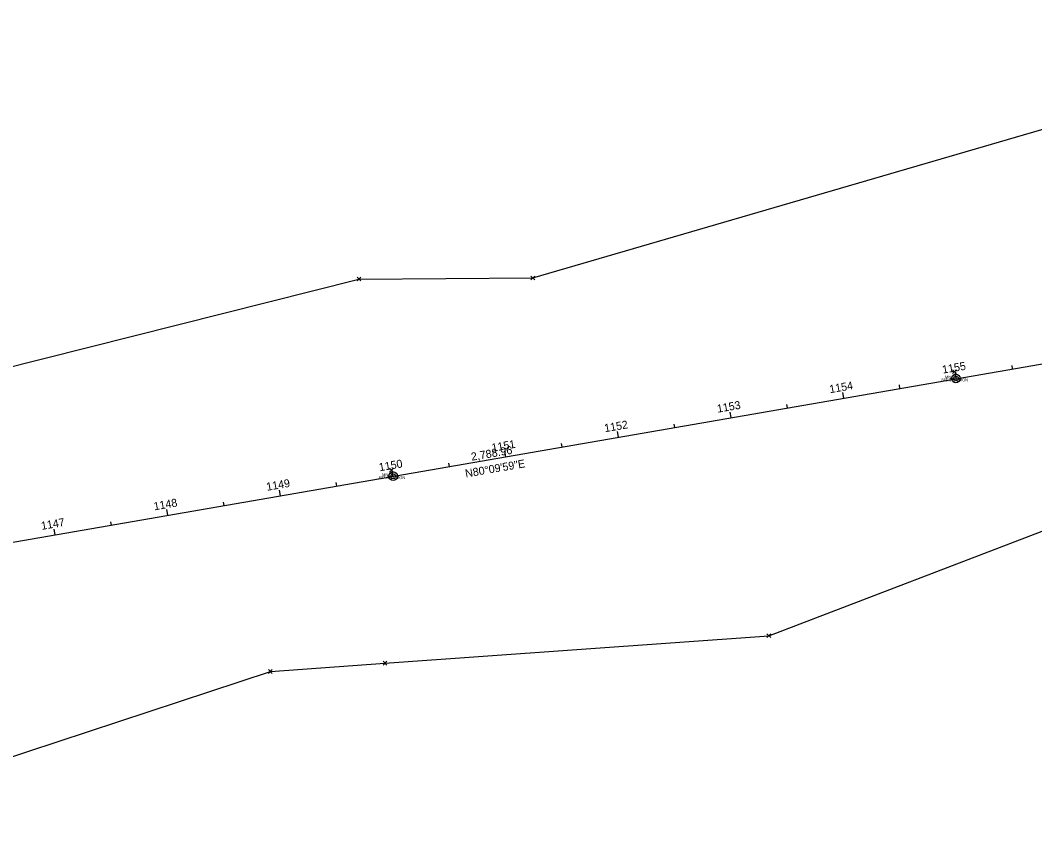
# Model space of a CAD drawing. Extents: x 2082101 to 2090447, y 708207 to 709766.
# Drawn here: x 2086260 to 2087148, y 708465 to 709174 of the extents above; entities that cross this region are included whole.
import ezdxf

# ---------------------------------------------------------------- set-up
doc = ezdxf.new("R2010")
doc.units = 0
for name, color, linetype in [('DR_X_Ditch', 7, 'Continuous'), ('GK_Drainage_Nodes', 7, 'Continuous'), ('SN_X_Public', 7, 'Continuous'), ('SV_X_Break_Lines', 7, 'Continuous'), ('SV_X_Mon_Cells_Found', 7, 'Continuous'), ('SV_X_Shot_Marker', 7, 'Continuous'), ('SV_X_Text_Comment', 7, 'Continuous'), ('SV_X_Text_Elevation', 7, 'Continuous'), ('SV_X_Text_Name', 7, 'Continuous'), ('SV_X_Toe_of_Slope', 7, 'Continuous'), ('VG_X_Cells', 7, 'Continuous')]:
    doc.layers.add(name, color=color, linetype=linetype)

msp = doc.modelspace()

# ---------------------------------------------------------------- linework, layer by layer
at = {"layer": 'DR_X_Ditch'}
for p, q in [((2086708.85, 708948.54), (2087481.72, 709173.84)), ((2085846.9, 708768.68), (2086556.78, 708947.55)), ((2086556.78, 708947.55), (2086708.85, 708948.54)), ((2086915.31, 708635.7), (2087248.47, 708762.97)), ((2086579.5, 708611.61), (2086915.31, 708635.7)), ((2086056.84, 708465.14), (2086479.26, 708604.37)), ((2086479.26, 708604.37), (2086579.5, 708611.61))]:
    msp.add_line(p, q, dxfattribs=at)
at = {"layer": 'GK_Drainage_Nodes'}
for p, q in [((2087128.59, 708869.05), (2087128.07, 708872.01)), ((2087079.32, 708860.51), (2087078.47, 708865.44)), ((2087030.06, 708851.98), (2087029.54, 708854.93)), ((2086980.79, 708843.44), (2086979.94, 708848.36)), ((2086931.52, 708834.9), (2086931.01, 708837.85)), ((2086882.26, 708826.36), (2086881.41, 708831.28)), ((2086832.99, 708817.82), (2086832.48, 708820.77)), ((2086783.73, 708809.28), (2086782.87, 708814.21)), ((2086734.46, 708800.74), (2086733.95, 708803.7)), ((2086685.2, 708792.2), (2086684.34, 708797.13)), ((2086635.93, 708783.66), (2086635.42, 708786.62)), ((2086586.67, 708775.12), (2086585.81, 708780.05)), ((2086488.14, 708758.04), (2086487.28, 708762.97)), ((2086537.4, 708766.58), (2086536.89, 708769.54)), ((2086389.61, 708740.96), (2086388.75, 708745.89)), ((2086438.87, 708749.5), (2086438.36, 708752.46)), ((2086291.07, 708723.89), (2086290.22, 708728.81)), ((2086340.34, 708732.42), (2086339.83, 708735.38))]:
    msp.add_line(p, q, dxfattribs=at)
at = {"layer": 'SV_X_Break_Lines'}
for p, q in [((2086707.18, 708946.87), (2086710.51, 708950.2)), ((2086707.18, 708950.2), (2086710.51, 708946.87)), ((2086555.11, 708945.88), (2086558.45, 708949.22)), ((2086555.11, 708949.22), (2086558.45, 708945.88)), ((2086913.64, 708634.03), (2086916.97, 708637.37)), ((2086913.64, 708637.37), (2086916.97, 708634.03)), ((2086577.84, 708609.94), (2086581.17, 708613.28)), ((2086577.84, 708613.28), (2086581.17, 708609.94)), ((2086477.6, 708602.7), (2086480.93, 708606.04)), ((2086477.6, 708606.04), (2086480.93, 708602.7))]:
    msp.add_line(p, q, dxfattribs=at)
at = {"layer": 'SV_X_Shot_Marker'}
msp.add_line((2085301.62, 708552.38), (2088049.6, 709028.7), dxfattribs=at)
at = {"layer": 'SV_X_Text_Name'}
for p, q in [((2087076.04, 708864.85), (2087079.38, 708868.19)), ((2087076.04, 708868.19), (2087079.38, 708864.85)), ((2086583.5, 708778.8), (2086586.84, 708782.13)), ((2086583.5, 708782.13), (2086586.84, 708778.8))]:
    msp.add_line(p, q, dxfattribs=at)
at = {"layer": 'SV_X_Toe_of_Slope'}
for centre, radius in [((2087079.01, 708860.62), 3.75), ((2087079.01, 708860.62), 2), ((2086586.66, 708775.09), 3.75), ((2086586.66, 708775.09), 2)]:
    msp.add_circle(centre, radius, dxfattribs=at)

# ---------------------------------------------------------------- texts
at = {"layer": 'GK_Drainage_Nodes'}
for s, p in [('1155', (2087067.6, 708864.83)), ('1154', (2086968.89, 708847.72)), ('1153', (2086870.56, 708830.67)), ('1152', (2086772, 708813.59)), ('1151', (2086673.44, 708796.5)), ('1150', (2086574.8, 708779.41)), ('1149', (2086476.37, 708762.35)), ('1148', (2086377.78, 708745.26)), ('1147', (2086279.27, 708728.18))]:
    msp.add_text(s, height=7, rotation=9.83357, dxfattribs=at).set_placement(p)
at = {"layer": 'SN_X_Public'}
msp.add_text('N80°09\'59"E', height=7, rotation=9.83357, dxfattribs=at).set_placement((2086650.27, 708773.97))
at = {"layer": 'SV_X_Mon_Cells_Found'}
for p in [(2087079.01, 708858.12), (2086586.66, 708772.59)]:
    msp.add_text('CMON', height=2.5, dxfattribs=at).set_placement(p)
at = {"layer": 'SV_X_Text_Comment'}
for s, p in [('885.959', (2087066.3, 708858.12)), ('897.681', (2086573.96, 708772.59))]:
    msp.add_text(s, height=2.5, dxfattribs=at).set_placement(p)
at = {"layer": 'SV_X_Text_Elevation'}
for s, p in [('MN19', (2087069.4, 708860.62)), ('MN18', (2086577.01, 708775.09))]:
    msp.add_text(s, height=2.5, dxfattribs=at).set_placement(p)
at = {"layer": 'VG_X_Cells'}
msp.add_text("2,788.96'", height=7, rotation=9.83357, dxfattribs=at).set_placement((2086655.41, 708788.62))

doc.saveas('drawing.dxf')
